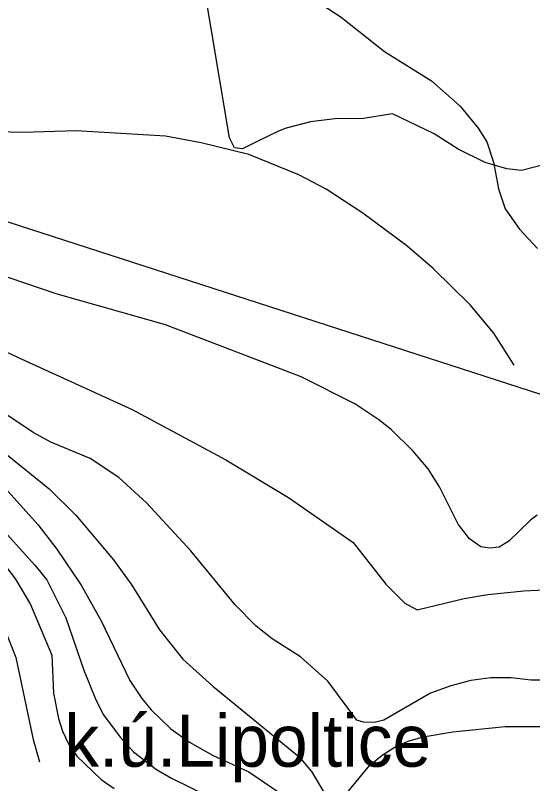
# Model space of a CAD drawing. Extents: x -662620 to -656370, y -1067090 to -1062990.
# Drawn here: x -661470.7 to -661271.5, y -1065210.9 to -1064915.2 of the extents above; entities that cross this region are included whole.
import ezdxf

# ---------------------------------------------------------------- set-up
doc = ezdxf.new("R2010")
doc.units = 0
for name, color, linetype in [('NÁZEV_K__Ú_', 7, 'Continuous'), ('SDELOVACÍ_VEDENÍ_-_PODZEMNÍ', 7, 'Continuous'), ('SILNICE_II__TŘÍDY_A_III__TŘÍDY', 7, 'Continuous'), ('VRSTEVNICE_ZDŮRAZNĚNÁ', 7, 'Continuous'), ('VRSTEVNICE_ZÁKLADNÍ', 7, 'Continuous')]:
    doc.layers.add(name, color=color, linetype=linetype)

msp = doc.modelspace()

# ---------------------------------------------------------------- linework, layer by layer
at = {"layer": 'SDELOVACÍ_VEDENÍ_-_PODZEMNÍ'}
for points in [[(-661377.78, -1064963.89), (-661383.23, -1064966.51), (-661386.26, -1064966.2), (-661388.23, -1064962.34), (-661402.6, -1064876.55), (-661406.33, -1064848.62)], [(-661377.78, -1064963.89), (-661383.23, -1064966.51), (-661386.26, -1064966.2), (-661388.23, -1064962.34), (-661402.6, -1064876.55), (-661406.33, -1064848.62)], [(-661377.78, -1064963.89), (-661383.23, -1064966.51), (-661386.26, -1064966.2), (-661388.23, -1064962.34), (-661402.6, -1064876.55), (-661406.33, -1064848.62)], [(-661377.78, -1064963.89), (-661383.23, -1064966.51), (-661386.26, -1064966.2), (-661388.23, -1064962.34), (-661402.6, -1064876.55), (-661406.33, -1064848.62)], [(-661377.78, -1064963.89), (-661383.23, -1064966.51), (-661386.26, -1064966.2), (-661388.23, -1064962.34), (-661402.6, -1064876.55), (-661406.33, -1064848.62)], [(-661377.78, -1064963.89), (-661383.23, -1064966.51), (-661386.26, -1064966.2), (-661388.23, -1064962.34), (-661402.6, -1064876.55), (-661406.33, -1064848.62)], [(-661300.19, -1064966.75), (-661309.37, -1064960.83), (-661325.48, -1064953.14), (-661336.65, -1064954.87), (-661347.64, -1064954.99), (-661357.03, -1064956.13), (-661366.42, -1064958.67), (-661369.26, -1064959.78), (-661377.78, -1064963.89)], [(-661300.19, -1064966.75), (-661309.37, -1064960.83), (-661325.48, -1064953.14), (-661336.65, -1064954.87), (-661347.64, -1064954.99), (-661357.03, -1064956.13), (-661366.42, -1064958.67), (-661369.26, -1064959.78), (-661377.78, -1064963.89)], [(-661300.19, -1064966.75), (-661309.37, -1064960.83), (-661325.48, -1064953.14), (-661336.65, -1064954.87), (-661347.64, -1064954.99), (-661357.03, -1064956.13), (-661366.42, -1064958.67), (-661369.26, -1064959.78), (-661377.78, -1064963.89)], [(-661300.19, -1064966.75), (-661309.37, -1064960.83), (-661325.48, -1064953.14), (-661336.65, -1064954.87), (-661347.64, -1064954.99), (-661357.03, -1064956.13), (-661366.42, -1064958.67), (-661369.26, -1064959.78), (-661377.78, -1064963.89)], [(-661300.19, -1064966.75), (-661309.37, -1064960.83), (-661325.48, -1064953.14), (-661336.65, -1064954.87), (-661347.64, -1064954.99), (-661357.03, -1064956.13), (-661366.42, -1064958.67), (-661369.26, -1064959.78), (-661377.78, -1064963.89)], [(-661300.19, -1064966.75), (-661309.37, -1064960.83), (-661325.48, -1064953.14), (-661336.65, -1064954.87), (-661347.64, -1064954.99), (-661357.03, -1064956.13), (-661366.42, -1064958.67), (-661369.26, -1064959.78), (-661377.78, -1064963.89)], [(-661218.87, -1064993.53), (-661227.86, -1064989.48), (-661235.62, -1064987.34), (-661238.68, -1064986.05), (-661244.96, -1064982.91), (-661248.01, -1064980.7), (-661252.96, -1064977.69), (-661267.26, -1064972.66), (-661275.69, -1064974.89), (-661281.39, -1064974.24), (-661289.67, -1064971.84), (-661300.19, -1064966.75)], [(-661218.87, -1064993.53), (-661227.86, -1064989.48), (-661235.62, -1064987.34), (-661238.68, -1064986.05), (-661244.96, -1064982.91), (-661248.01, -1064980.7), (-661252.96, -1064977.69), (-661267.26, -1064972.66), (-661275.69, -1064974.89), (-661281.39, -1064974.24), (-661289.67, -1064971.84), (-661300.19, -1064966.75)], [(-661218.87, -1064993.53), (-661227.86, -1064989.48), (-661235.62, -1064987.34), (-661238.68, -1064986.05), (-661244.96, -1064982.91), (-661248.01, -1064980.7), (-661252.96, -1064977.69), (-661267.26, -1064972.66), (-661275.69, -1064974.89), (-661281.39, -1064974.24), (-661289.67, -1064971.84), (-661300.19, -1064966.75)], [(-661218.87, -1064993.53), (-661227.86, -1064989.48), (-661235.62, -1064987.34), (-661238.68, -1064986.05), (-661244.96, -1064982.91), (-661248.01, -1064980.7), (-661252.96, -1064977.69), (-661267.26, -1064972.66), (-661275.69, -1064974.89), (-661281.39, -1064974.24), (-661289.67, -1064971.84), (-661300.19, -1064966.75)], [(-661218.87, -1064993.53), (-661227.86, -1064989.48), (-661235.62, -1064987.34), (-661238.68, -1064986.05), (-661244.96, -1064982.91), (-661248.01, -1064980.7), (-661252.96, -1064977.69), (-661267.26, -1064972.66), (-661275.69, -1064974.89), (-661281.39, -1064974.24), (-661289.67, -1064971.84), (-661300.19, -1064966.75)], [(-661218.87, -1064993.53), (-661227.86, -1064989.48), (-661235.62, -1064987.34), (-661238.68, -1064986.05), (-661244.96, -1064982.91), (-661248.01, -1064980.7), (-661252.96, -1064977.69), (-661267.26, -1064972.66), (-661275.69, -1064974.89), (-661281.39, -1064974.24), (-661289.67, -1064971.84), (-661300.19, -1064966.75)]]:
    msp.add_lwpolyline(points, dxfattribs=at)
at = {"layer": 'SILNICE_II__TŘÍDY_A_III__TŘÍDY'}
msp.add_lwpolyline([(-659930.63, -1065272.66), (-659916.62, -1065191.45), (-659883.02, -1065082.94), (-660018.13, -1065073.84), (-660053.14, -1065071.74), (-660090.24, -1065065.44), (-660211.35, -1065031.14), (-660237.25, -1065024.84), (-660258.96, -1065021.34), (-660284.16, -1065023.44), (-661097.31, -1065116.39), (-661512.77, -1064982.13)], dxfattribs=at)
at = {"layer": 'VRSTEVNICE_ZDŮRAZNĚNÁ'}
for points in [[(-661497.95, -1065033.58), (-661469.85, -1065046.76), (-661425.7, -1065066.83), (-661389.58, -1065086.19), (-661365.49, -1065100.81), (-661340.55, -1065118.01), (-661327.93, -1065134.07), (-661320.62, -1065141.38), (-661315.89, -1065143.96), (-661297.83, -1065139.66), (-661288.65, -1065138.08), (-661274.89, -1065136.65), (-661256.54, -1065135.79)], [(-661474.3, -1065127.33), (-661470.57, -1065132.2), (-661464.84, -1065141.95), (-661456.67, -1065161.45), (-661455.95, -1065176.07), (-661454.08, -1065185.82), (-661452.51, -1065190.69), (-661450.21, -1065195.57), (-661446.92, -1065200.3), (-661437.6, -1065209.33), (-661432.58, -1065212.77)]]:
    msp.add_lwpolyline(points, dxfattribs=at)
at = {"layer": 'VRSTEVNICE_ZÁKLADNÍ'}
for points in [[(-661463.35, -1064909.94), (-661437.46, -1064900.11), (-661421.97, -1064895.81), (-661412.51, -1064894.38), (-661403.05, -1064893.8), (-661394.45, -1064894.09), (-661384.41, -1064896.24), (-661368.71, -1064902.03), (-661358.04, -1064907.42), (-661345.14, -1064915.88), (-661328.51, -1064929.07), (-661310.44, -1064940.4), (-661299.41, -1064950.14), (-661292.38, -1064958.6), (-661289.08, -1064963.91), (-661286.5, -1064971.65), (-661284.64, -1064981.97), (-661282.06, -1064989.71), (-661276.47, -1064997.45), (-661269.59, -1065004.9)], [(-661463.35, -1064909.94), (-661437.46, -1064900.11), (-661421.97, -1064895.81), (-661412.51, -1064894.38), (-661403.05, -1064893.8), (-661394.45, -1064894.09), (-661384.41, -1064896.24), (-661368.71, -1064902.03), (-661358.04, -1064907.42), (-661345.14, -1064915.88), (-661328.51, -1064929.07), (-661310.44, -1064940.4), (-661299.41, -1064950.14), (-661292.38, -1064958.6), (-661289.08, -1064963.91), (-661286.5, -1064971.65), (-661284.64, -1064981.97), (-661282.06, -1064989.71), (-661276.47, -1064997.45), (-661269.59, -1065004.9)], [(-661278.59, -1065049.76), (-661286.36, -1065037.45), (-661295.53, -1065026.55), (-661309.73, -1065012.65), (-661319.91, -1065003.9), (-661336.82, -1064991.29), (-661351.01, -1064982.11), (-661361.48, -1064976.52), (-661380.69, -1064968.78), (-661399.04, -1064964.19), (-661412.8, -1064961.75), (-661447.2, -1064959.6), (-661467.85, -1064960.32), (-661477.59, -1064960.03), (-661482.76, -1064959.03), (-661495.66, -1064955.02), (-661503.4, -1064953.58), (-661505.98, -1064953.58), (-661513.72, -1064955.3), (-661518.88, -1064957.88), (-661526.48, -1064963.47), (-661532.5, -1064968.92)], [(-661278.59, -1065049.76), (-661286.36, -1065037.45), (-661295.53, -1065026.55), (-661309.73, -1065012.65), (-661319.91, -1065003.9), (-661336.82, -1064991.29), (-661351.01, -1064982.11), (-661361.48, -1064976.52), (-661380.69, -1064968.78), (-661399.04, -1064964.19), (-661412.8, -1064961.75), (-661447.2, -1064959.6), (-661467.85, -1064960.32), (-661477.59, -1064960.03), (-661482.76, -1064959.03), (-661495.66, -1064955.02), (-661503.4, -1064953.58), (-661505.98, -1064953.58), (-661513.72, -1064955.3), (-661518.88, -1064957.88), (-661526.48, -1064963.47), (-661532.5, -1064968.92)], [(-661269.73, -1065107.55), (-661272.31, -1065109.41), (-661280.63, -1065117.58), (-661284.35, -1065119.87), (-661288.08, -1065120.3), (-661291.38, -1065119.73), (-661295.71, -1065116.66), (-661300.15, -1065110.96), (-661307.29, -1065096.65), (-661311.73, -1065089.77), (-661317.47, -1065082.89), (-661325.78, -1065074.72), (-661330.66, -1065070.85), (-661339.97, -1065064.68), (-661360.62, -1065054.36), (-661412.8, -1065034.29), (-661454.95, -1065022.39), (-661484.48, -1065012.36)], [(-661269.73, -1065107.55), (-661272.31, -1065109.41), (-661280.63, -1065117.58), (-661284.35, -1065119.87), (-661288.08, -1065120.3), (-661291.38, -1065119.73), (-661295.71, -1065116.66), (-661300.15, -1065110.96), (-661307.29, -1065096.65), (-661311.73, -1065089.77), (-661317.47, -1065082.89), (-661325.78, -1065074.72), (-661330.66, -1065070.85), (-661339.97, -1065064.68), (-661360.62, -1065054.36), (-661412.8, -1065034.29), (-661454.95, -1065022.39), (-661484.48, -1065012.36)], [(-661261.7, -1065171.05), (-661272.03, -1065171.05), (-661279.77, -1065170.19), (-661287.51, -1065170.19), (-661295.25, -1065171.2), (-661302.99, -1065173.2), (-661310.73, -1065176.07), (-661328.79, -1065186.39), (-661332.38, -1065187.39), (-661336.53, -1065187.25), (-661339.11, -1065186.39), (-661350.3, -1065171.48), (-661360.9, -1065162.02), (-661371.8, -1065155.14), (-661377.96, -1065150.27), (-661385.99, -1065142.09), (-661403.05, -1065121.31), (-661420.11, -1065102.82), (-661430.86, -1065093.07), (-661441.9, -1065085.76), (-661456.95, -1065079.45), (-661463.83, -1065075.72), (-661474.73, -1065068.41)], [(-661261.7, -1065171.05), (-661272.03, -1065171.05), (-661279.77, -1065170.19), (-661287.51, -1065170.19), (-661295.25, -1065171.2), (-661302.99, -1065173.2), (-661310.73, -1065176.07), (-661328.79, -1065186.39), (-661332.38, -1065187.39), (-661336.53, -1065187.25), (-661339.11, -1065186.39), (-661350.3, -1065171.48), (-661360.9, -1065162.02), (-661371.8, -1065155.14), (-661377.96, -1065150.27), (-661385.99, -1065142.09), (-661403.05, -1065121.31), (-661420.11, -1065102.82), (-661430.86, -1065093.07), (-661441.9, -1065085.76), (-661456.95, -1065079.45), (-661463.83, -1065075.72), (-661474.73, -1065068.41)], [(-661474.44, -1065083.75), (-661457.67, -1065097.37), (-661447.35, -1065107.55), (-661432.87, -1065124.75), (-661425.84, -1065134.5), (-661415.09, -1065151.7), (-661406.2, -1065163.02), (-661394.59, -1065173.35), (-661361.33, -1065200.58), (-661356.6, -1065206.17), (-661351.44, -1065214.77)], [(-661474.44, -1065083.75), (-661457.67, -1065097.37), (-661447.35, -1065107.55), (-661432.87, -1065124.75), (-661425.84, -1065134.5), (-661415.09, -1065151.7), (-661406.2, -1065163.02), (-661394.59, -1065173.35), (-661361.33, -1065200.58), (-661356.6, -1065206.17), (-661351.44, -1065214.77)], [(-661475.73, -1065095.93), (-661461.97, -1065111.13), (-661454.66, -1065120.59), (-661445.34, -1065134.5), (-661437.6, -1065148.26), (-661426.56, -1065171.2), (-661421.97, -1065178.08), (-661418.39, -1065182.52), (-661410.79, -1065189.83), (-661403.62, -1065194.85), (-661394.74, -1065199.87), (-661380.69, -1065206.32), (-661368.65, -1065214.49)], [(-661475.73, -1065095.93), (-661461.97, -1065111.13), (-661454.66, -1065120.59), (-661445.34, -1065134.5), (-661437.6, -1065148.26), (-661426.56, -1065171.2), (-661421.97, -1065178.08), (-661418.39, -1065182.52), (-661410.79, -1065189.83), (-661403.62, -1065194.85), (-661394.74, -1065199.87), (-661380.69, -1065206.32), (-661368.65, -1065214.49)], [(-661478.6, -1065109.84), (-661463.12, -1065126.76), (-661458.53, -1065132.49), (-661451.22, -1065147.11), (-661444.34, -1065167.18), (-661439.6, -1065178.65), (-661436.74, -1065184.38), (-661430.29, -1065192.98), (-661425.13, -1065198.58), (-661416.24, -1065205.46), (-661410.51, -1065208.75), (-661389.86, -1065218.93)], [(-661478.6, -1065109.84), (-661463.12, -1065126.76), (-661458.53, -1065132.49), (-661451.22, -1065147.11), (-661444.34, -1065167.18), (-661439.6, -1065178.65), (-661436.74, -1065184.38), (-661430.29, -1065192.98), (-661425.13, -1065198.58), (-661416.24, -1065205.46), (-661410.51, -1065208.75), (-661389.86, -1065218.93)], [(-661476.16, -1065147.97), (-661470.43, -1065162.31), (-661463.83, -1065193.85), (-661461.4, -1065202.45)], [(-661476.16, -1065147.97), (-661470.43, -1065162.31), (-661463.83, -1065193.85), (-661461.4, -1065202.45)], [(-661344.99, -1065216.78), (-661334.1, -1065203.74), (-661329.37, -1065199.87), (-661324.78, -1065197), (-661319.33, -1065194.56), (-661313.6, -1065192.84), (-661302.13, -1065190.98), (-661282.06, -1065188.83), (-661262.56, -1065188.83), (-661241.92, -1065191.55), (-661202.93, -1065198.15), (-661189.17, -1065202.16), (-661157.05, -1065215.63)], [(-661344.99, -1065216.78), (-661334.1, -1065203.74), (-661329.37, -1065199.87), (-661324.78, -1065197), (-661319.33, -1065194.56), (-661313.6, -1065192.84), (-661302.13, -1065190.98), (-661282.06, -1065188.83), (-661262.56, -1065188.83), (-661241.92, -1065191.55), (-661202.93, -1065198.15), (-661189.17, -1065202.16), (-661157.05, -1065215.63)]]:
    msp.add_lwpolyline(points, dxfattribs=at)

# ---------------------------------------------------------------- texts
at = {"layer": 'NÁZEV_K__Ú_'}
msp.add_text('k.ú.Lipoltice', height=20, dxfattribs=at).set_placement((-661451.78, -1065204.35))

doc.saveas('drawing.dxf')
